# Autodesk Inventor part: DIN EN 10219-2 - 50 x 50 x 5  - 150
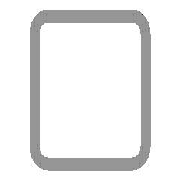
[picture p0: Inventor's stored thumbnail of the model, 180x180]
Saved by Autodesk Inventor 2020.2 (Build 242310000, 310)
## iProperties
Created: 2019-01
Part Number: DIN EN 10219-2 - 50 x 50 x 5  - 150
Material: Generisch
Description: Kaltgeformte, geschweißte Baustahl-Hohlprofile aus unlegiertem Feinkorn-Baustahl
Document SubType Name: Modeling
Standard: DIN
Designer: lutzd
Standard Revision: 2006-07
Standards Organization: DIN
Language: de-DE
Size Designation: 50 x 50 x 5
Categories: <MemberInstance><Categories><Category DisplayName="Profile" InternalName="089c4875-fa83-4c05-b084-43b9cc11f5ed" Mnemonic="GRDR"><CategoryParameter DisplayName="
Stock Number: 50 x 50 x 5
Mass: 125.343 g
Surface Area: 518.084 cm^2
Volume: 125.343 cm^3
Density: 1 g/cm^3
Appearance: Vorgabe
_CCFamilyMember: 16
_CCFamilyDisplayName: DIN EN 10219-2 (Quadratisches Hohlprofil - Kaltgeformt) - Kaltgeformte, geschweißte Baustahl-Hohlprofile aus unlegiertem Feinkorn-Baustahl
_FrameMemberDoc: Frame Member File
_Version: 15.0.0
_GetPNFromCC: 1
G_L: 150,000 mm
G_W: 50,000 mm
G_H: 50,000 mm
Mass: 0,125 kg
VLT_Material: Generisch
+3E19A106-FFEB-41EE-B559-30A5E9D5CD99+SCHNITTDETAIL1: Schnittwinkel 90,00 grd
DocNumber: ADSK-014441
Folder: .
Dimensions: 50x50x150 mm
IsCustomPart: 1
Title: Profil-Bauteil
Author: lutzd
Revision Number: -
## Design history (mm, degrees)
node "Startebene"
node "Endebene"
sketch "Skizze"
  geometry: L1 (-25, -15)-(-25, 15); L2 (-15, 25)-(15, 25); L3 (25, 15)-(25, -15); L4 (15, -25)-(-15, -25); L5 (-15, 20)-(15, 20); L6 (20, 15)-(20, -15); L7 (15, -20)-(-15, -20); L8 (-20, -15)-(-20, 15); L9 (0, 37.899)-(0, -37.899) reference; L10 (-37.899, 0)-(37.899, 0) reference; A1 r 10 centre (-15, -15) between (-25, -15) and (-15, -25); A2 r 10 centre (-15, 15) between (-15, 25) and (-25, 15); A3 r 10 centre (15, 15) between (25, 15) and (15, 25); A4 r 10 centre (15, -15) between (15, -25) and (25, -15); A5 r 5 centre (-15, 15) between (-15, 20) and (-20, 15); A6 r 5 centre (15, 15) between (20, 15) and (15, 20); A7 r 5 centre (15, -15) between (15, -20) and (20, -15); A8 r 5 centre (-15, -15) between (-20, -15) and (-15, -20)
  constraints: 16 end point, 16 point on circle, 8 centre point, 8 tangent, 4 parallel, 3 equal radius, 2 perpendicular, 7 other
  dimensions: "d7" = 10 radius of A1 (= G_IR); "d10" = 50 distance between parallel lines of L2 L4 (= G_H); "d11" = 50 distance between parallel lines of L1 L3 (= G_W); "d12" = 5 distance between parallel lines of L3 L6 (= G_T); "d15" = 25 distance between parallel lines of L2 L10 (= 0.5 x d10); "d16" = 25 distance between parallel lines of L9 L3 (= 0.5 x d11)
extrude "Körper" new body sketch "Skizze" stored distance "d3" = 150 (= G_L); taper "d4" = 0 deg
node "Driven Length"
  sketch "Sketch3"
    geometry: L1 (0, 0)-(10, 0) reference
    constraints: 2 end point, 1 horizontal
  workplane "Work Plane3"
  sketch "Sketch4"
    geometry: L1 (-2, 0)-(12, 0) reference; L2 (-2, 150)-(12, 150) reference
    dimensions: "d18" = 150 distance between parallel lines of L1 L2 (derived)
workplane "Arbeitsebene4"
feature "Trennen1"
body "Solid1"
other parameters: "G_W" = 50 [user parameter; used in 1 equation term], "G_H" = 50 [user parameter; used in 1 equation term], "G_T" = 5 [user parameter; used in 1 equation term], "G_IR" = 10 [user parameter; used in 1 equation term], "G_L" = 150 (= d18) [user parameter; used in 1 equation term], "G_OFFSET_START" = 0 [user parameter; used in 1 equation term], "d13" = 0 (computed from G_OFFSET_START), "d17" = 90 deg
